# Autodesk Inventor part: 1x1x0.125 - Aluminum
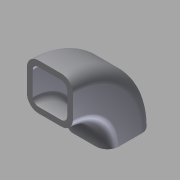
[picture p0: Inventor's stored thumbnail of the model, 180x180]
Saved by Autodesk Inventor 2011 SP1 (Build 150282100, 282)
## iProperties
Created: 2011-03
Part Number: 1x1x0.125 - Aluminum
Document SubType Name: Modeling
Designer: bamfomg
Density: 1 g/cm^3
Author: bamfomg
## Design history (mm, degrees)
sketch "Sketch1"
  geometry: L1 (-6.35, 12.7)-(6.35, 12.7); L2 (12.7, 6.35)-(12.7, -6.35); L3 (6.35, -12.7)-(-6.35, -12.7); L4 (-12.7, -6.35)-(-12.7, 6.35); L5 (-6.35, 9.525)-(6.35, 9.525); L6 (9.525, 6.35)-(9.525, -6.35); L7 (6.35, -9.525)-(-6.35, -9.525); L8 (-9.525, -6.35)-(-9.525, 6.35); L9 (-26.457, -31.75)-(36.725, -31.75); A1 r 6.35 centre (6.35, 6.35) between (12.7, 6.35) and (6.35, 12.7); A2 r 6.35 centre (6.35, -6.35) between (6.35, -12.7) and (12.7, -6.35); A3 r 6.35 centre (-6.35, -6.35) between (-12.7, -6.35) and (-6.35, -12.7); A4 r 6.35 centre (-6.35, 6.35) between (-6.35, 12.7) and (-12.7, 6.35); A5 r 3.175 centre (-6.35, 6.35) between (-6.35, 9.525) and (-9.525, 6.35); A6 r 3.175 centre (6.35, 6.35) between (9.525, 6.35) and (6.35, 9.525); A7 r 3.175 centre (6.35, -6.35) between (6.35, -9.525) and (9.525, -6.35); A8 r 3.175 centre (-6.35, -6.35) between (-9.525, -6.35) and (-6.35, -9.525); 4 further points
  constraints: 18 end point, 16 point on circle, 16 tangent, 8 centre point, 6 equal radius, 6 point on line, 4 parallel, 3 perpendicular, 2 horizontal
  dimensions: "Side_One" = 25.4 distance of point (-12.7, 12.7) point (12.7, 12.7); "Side_Two" = 25.4 distance of point (-12.7, -12.7) point (-12.7, 12.7); "d2" = 12.7 distance from line of point (0, 0) L4 (= 0.5 x Side_One); "d3" = 12.7 distance from line of point (0, 0) L1 (= 0.5 x Side_Two); "Thickness" = 3.175 distance between parallel lines of L1 L5; "d6" = 3.175 distance between parallel lines of L4 L8 (= Thickness); "d7" = 3.175 distance between parallel lines of L3 L7 (= Thickness); "d8" = 3.175 distance between parallel lines of L2 L6 (= Thickness); "OD_Rad" = 6.35 radius of A1; "ID_Rad" = 3.175 radius of A5; "Bend_IDRad" = 19.05 distance between parallel lines of L9 L3
revolve "Revolution1" sketch "Sketch1" stored, may be unused: angle "d12" = 90 deg
chamfer "Chamfer1" distance "Bevel_Dist" = 1.5875; stored, may be unused: second distance "d14" = 3.175, angle "Bevel_Angl" = 30 deg
chamfer "Chamfer2" distance "d16" = 1.5875 (= Bevel_Dist); stored, may be unused: second distance "d17" = 3.175, angle "d18" = 30 deg (= Bevel_Angl)
body "Solid1"
